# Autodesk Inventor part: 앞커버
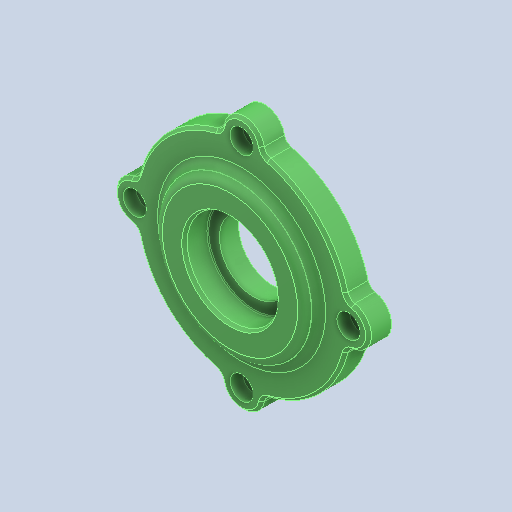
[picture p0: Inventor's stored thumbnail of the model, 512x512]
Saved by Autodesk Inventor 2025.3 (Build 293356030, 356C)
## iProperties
Created: 2025-08
Part Number: 앞커버
Material: 알루미늄 6061
Document SubType Name: Modeling
Designer: infra011
Density: 2.71 g/cm^3
Appearance: 기본값
Company: 한국ATC센터
Author: jhkim
Sending System: Autodesk Inventor 2026
Preprocessor: ST-DEVELOPER v20.1
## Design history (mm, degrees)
feature "솔리드1"
node "솔리드2"
